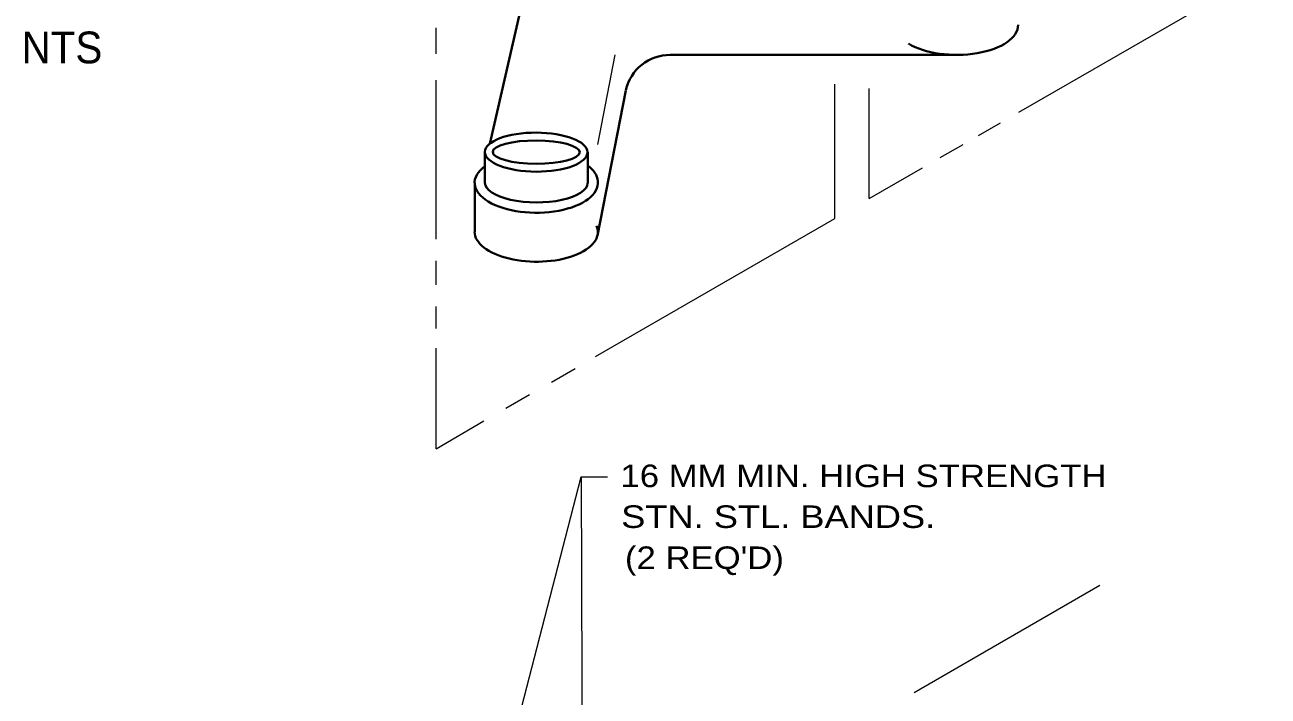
# Model space of a CAD drawing. Extents: x 312583 to 312854, y 144419 to 144597.
# Drawn here: x 312651.61 to 312693.46, y 144505.2 to 144527.81 of the extents above; entities that cross this region are included whole.
import ezdxf
from ezdxf.enums import TextEntityAlignment as Align

# ---------------------------------------------------------------- set-up
doc = ezdxf.new("R2010")
doc.units = 0
doc.header["$LTSCALE"] = 0.3
doc.layers.add('1', color=7, linetype='Continuous', lineweight=40)
doc.layers.add('2', color=7, linetype='Continuous', lineweight=40)

msp = doc.modelspace()

# ---------------------------------------------------------------- linework, layer by layer
at = {"layer": '1'}
for p, q in [((312667.2677, 144523.8063), (312668.6324, 144529.7863)), ((312682.9691, 144526.7963), (312673.3321, 144526.7963)), ((312670.8864, 144520.7167), (312671.8371, 144525.6003)), ((312667.0991, 144523.5227), (312667.0991, 144522.4877)), ((312670.5567, 144523.515), (312670.5567, 144522.48)), ((312666.7541, 144522.4877), (312666.7541, 144520.8393))]:
    msp.add_line(p, q, dxfattribs=at)
at = {"layer": '1', "lineweight": 13}
for p, q in [((312685.0774, 144524.8643), (312693.4647, 144529.7097)), ((312665.4507, 144526.827), (312665.4507, 144527.7087)), ((312670.8941, 144523.7757), (312671.4844, 144526.7963)), ((312665.4507, 144520.594), (312665.4507, 144525.9453)), ((312678.8827, 144521.2917), (312678.8827, 144525.815)), ((312680.0327, 144521.9587), (312680.0327, 144525.6693)), ((312683.7127, 144524.0823), (312684.4564, 144524.5117)), ((312682.4247, 144523.3387), (312683.1991, 144523.7833)), ((312680.0327, 144521.9587), (312681.8267, 144522.9937)), ((312670.8174, 144516.638), (312678.8827, 144521.2917)), ((312665.4507, 144519.053), (312665.4507, 144519.858)), ((312665.4507, 144517.581), (312665.4507, 144518.317)), ((312665.4507, 144513.533), (312665.4507, 144516.9217)), ((312669.3377, 144515.7793), (312670.1351, 144516.2393)), ((312667.8044, 144514.8977), (312668.6017, 144515.3577)), ((312665.4507, 144513.533), (312667.0607, 144514.4683)), ((312681.5431, 144505.322), (312687.7991, 144508.933))]:
    msp.add_line(p, q, dxfattribs=at)
at = {"layer": '1'}
msp.add_arc((312673.3341, 144525.263), 1.5333, 90, 167.1306, dxfattribs=at)
for centre, major_axis, ratio, start_param, end_param in [((312682.9714, 144527.8003), (2.0738, -0.0073), 0.484108, 3.8185075, 6.2976936), ((312668.8248, 144522.4842), (2.0738, -0.0073), 0.484108, 2.5572095, 6.3522032), ((312668.821, 144522.5248), (2.0738, -0.0073), 0.484108, 0.0285632, 0.5872246), ((312668.8248, 144522.4842), (1.7278, -0.0061), 0.380773, 3.1420774, 6.2836701), ((312668.8248, 144520.8336), (2.0738, -0.0073), 0.484108, 3.1415927, 6.4944796)]:
    msp.add_ellipse(centre, major_axis=major_axis, ratio=ratio, start_param=start_param, end_param=end_param, dxfattribs=at)
for major_axis, ratio in [((1.7278, -0.0061), 0.380773), ((1.4632, -0.0051), 0.268821)]:
    msp.add_ellipse((312668.8248, 144523.5208), major_axis=major_axis, ratio=ratio, dxfattribs=at)
at = {"layer": '2', "lineweight": 13}
msp.add_line((312670.3344, 144512.5823), (312671.2237, 144512.5823), dxfattribs=at)
msp.add_lwpolyline([(312666.1561, 144496.375), (312670.3344, 144512.5823), (312670.3804, 144498.7287)], dxfattribs=at)

# ---------------------------------------------------------------- texts
at = {"layer": '2', "width": 0.95}
msp.add_text('NTS', height=1.07, dxfattribs=at).set_placement((312652.8571, 144526.5119), align=Align.CENTER)
at = {"layer": '2'}
for s, width, p in [('16 MM MIN. HIGH STRENGTH', 1.15, (312671.6607, 144512.2379)), ('STN. STL. BANDS.', 1.2, (312671.6847, 144510.8644)), ("(2 REQ'D)", 1.15, (312671.8106, 144509.4809))]:
    msp.add_text(s, height=0.76, dxfattribs=dict(at, width=width)).set_placement(p)

doc.saveas('drawing.dxf')
